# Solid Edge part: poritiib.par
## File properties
Author: Stella-Marii
Template: Iso Metric Part.par
Last saved by: Stella-Marii
Revision: 1
Application: Solid Edge
Accuracy: 0,990
Username: Stella-Marii
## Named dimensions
BlueSurf_1: StartTangentMagnitude2 = 1.37609; StartTangentMagnitude3 = 1.37609; EndTangentMagnitude1 = 1; EndTangentMagnitude2 = 1.75155; EndTangentMagnitude3 = 1.73536
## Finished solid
Body 1: sheet body, 1 face, 4 edges, 4 vertices.
  Faces by surface: spline 1
  Edges by curve: circle 2, spline 2
Bounding box of the edges (mm; curved faces can reach further): 136.834 x 118.752 x 129.536, from (-136.8338, -118.7525, 0) to (0, 0, 129.536).
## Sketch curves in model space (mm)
arc centre (0, -59.3763, 29.536) radius 100 from (0, 0, 110) through (0, -59.3763, 129.536) to (0, -118.7525, 110)
arc centre (-76.8338, -50, 0) radius 60 from (-110, 0, 0) through (-136.807, -51.7908, 0) to (-110, -100, 0)
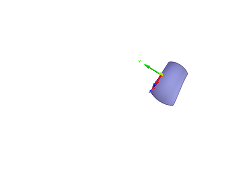
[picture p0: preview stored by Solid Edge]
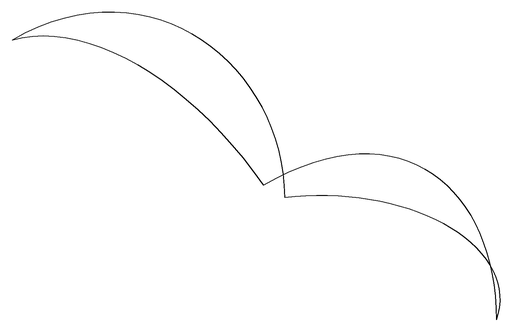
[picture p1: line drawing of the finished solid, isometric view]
